(* Logix 5000 project; controller logix5561 vendor 1 type 14 code 54 rev 19.11; software revision 19.01 *)

TASK MainTask (continuous, watchdog 500 ms) : MainProgram

MODULES
   Local : vendor 1 type 14 code 54 (ICP 0, rev 19.11)
      EIP : 1756-ENBT (ICP 1, Ethernet 192.168.16.199, rev 6.1)
         Fuji_Inverter : ETHERNET-MODULE (Ethernet 192.168.16.28, rev 1.1, Output RPI 10 ms)
END_MODULES

ADD_ON_INSTRUCTION OPCF1WIE_ACDC_Drive_Profile   (* revision 1.0 *)
// Interface for AC/DC Drive Profile that uses Input Assembly Instance 71 and Output Assembly Instance 21.
VAR_IN_OUT
   I_Data : INT[2]; {required}   // Input data
   O_Data : INT[2]; {required}   // Output data
END_VAR
VAR_INPUT
   RunForward : BOOL; {required}   // Run forward
   RunReverse : BOOL; {required}   // Run reverse
   ResetFault : BOOL; {required}   // Reset fault
   SpeedReference : INT; {access Read Only, required}   // Speed reference (RPM)
END_VAR
VAR_OUTPUT
   Faulted : BOOL; {access Read Only, visible}   // Faulted
   RunningForward : BOOL; {access Read Only, visible}   // Running forward
   RunningReverse : BOOL; {access Read Only, visible}   // Running reverse
   Ready : BOOL; {access Read Only, visible}   // Ready
   AtReference : BOOL; {access Read Only, visible}   // Up-to-speed
   DriveState : SINT; {access Read Only, visible}   // Drive state (0 = vendor specific, 1 = startup, 2 = not ready, 3 = ready, 4 = enabled, 5 = stopping, 6 = fault stop, 7 = faulted)
   SpeedActual : INT; {access Read Only, visible}   // Actual speed (RPM)
END_VAR
VAR
   temp : INT; {access None}
END_VAR

ROUTINE Logic   (* ladder *)
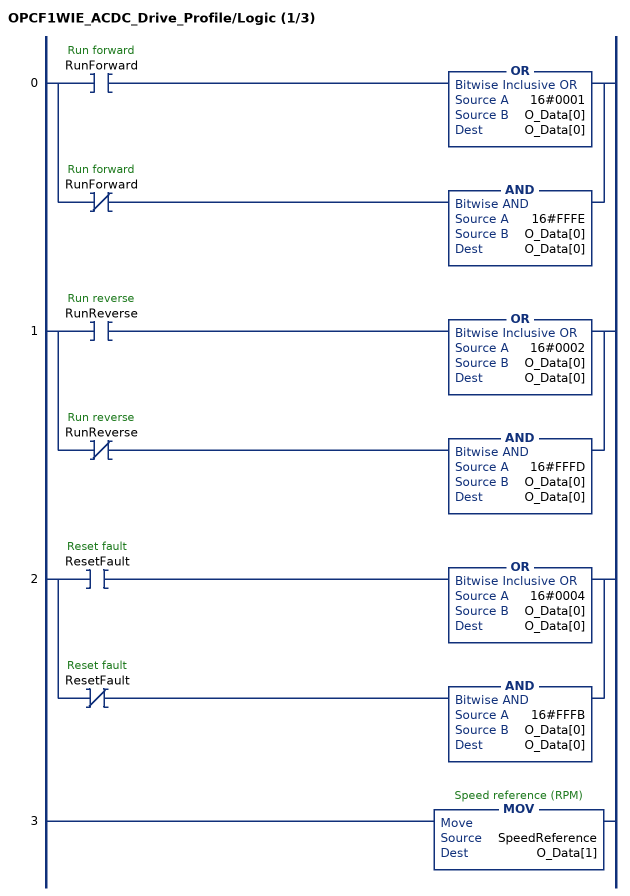
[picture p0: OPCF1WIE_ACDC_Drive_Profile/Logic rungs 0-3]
   0: [XIC(RunForward) OR(16#0001,O_Data[0],O_Data[0]) ,XIO(RunForward) AND(16#FFFE,O_Data[0],O_Data[0]) ];
   1: [XIC(RunReverse) OR(16#0002,O_Data[0],O_Data[0]) ,XIO(RunReverse) AND(16#FFFD,O_Data[0],O_Data[0]) ];
   2: [XIC(ResetFault) OR(16#0004,O_Data[0],O_Data[0]) ,XIO(ResetFault) AND(16#FFFB,O_Data[0],O_Data[0]) ];
   3: MOV(SpeedReference,O_Data[1]);
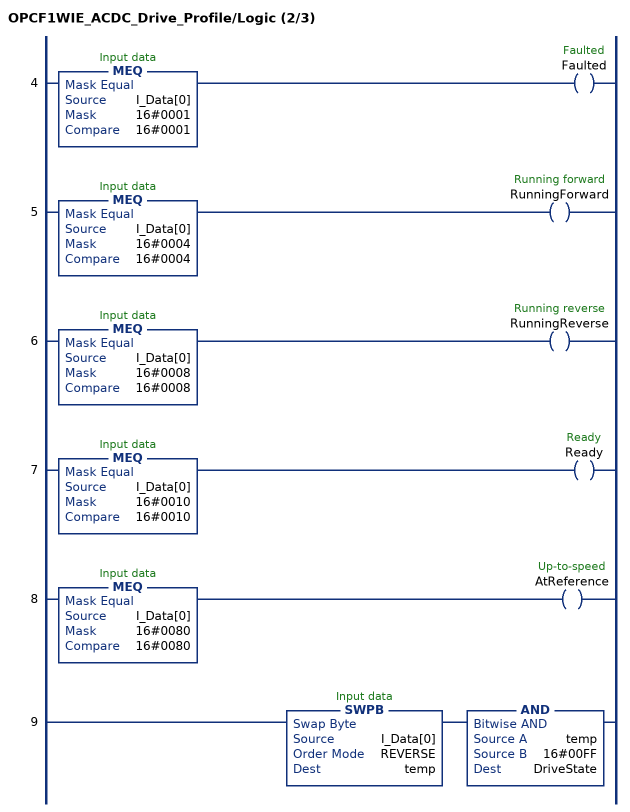
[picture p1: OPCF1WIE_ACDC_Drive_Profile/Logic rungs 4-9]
   4: MEQ(I_Data[0],16#0001,16#0001)OTE(Faulted);
   5: MEQ(I_Data[0],16#0004,16#0004)OTE(RunningForward);
   6: MEQ(I_Data[0],16#0008,16#0008)OTE(RunningReverse);
   7: MEQ(I_Data[0],16#0010,16#0010)OTE(Ready);
   8: MEQ(I_Data[0],16#0080,16#0080)OTE(AtReference);
   9: SWPB(I_Data[0],REVERSE,temp)AND(temp,16#00FF,DriveState);
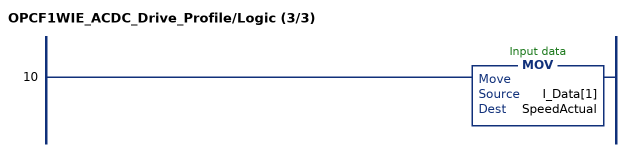
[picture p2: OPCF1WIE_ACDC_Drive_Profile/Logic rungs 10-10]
   10: MOV(I_Data[1],SpeedActual);
END_ROUTINE
END_ADD_ON_INSTRUCTION

VAR_GLOBAL   (* controller tags *)
   acdc_aoi : OPCF1WIE_ACDC_Drive_Profile;
   reset : BOOL;   // Fault reset
   run_fwd : BOOL;   // Run forward direction
   run_rev : BOOL;   // Run reverse direction
   speed_ref : INT := 1370;   // Speed reference (RPM)
END_VAR

PROGRAM MainProgram   (* main routine MainRoutine *)

ROUTINE MainRoutine   (* ladder *)
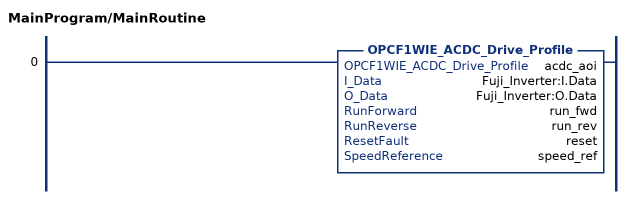
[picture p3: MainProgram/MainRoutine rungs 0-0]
   0: OPCF1WIE_ACDC_Drive_Profile(acdc_aoi,Fuji_Inverter:I.Data,Fuji_Inverter:O.Data,run_fwd,run_rev,reset,speed_ref);
END_ROUTINE
END_PROGRAM
